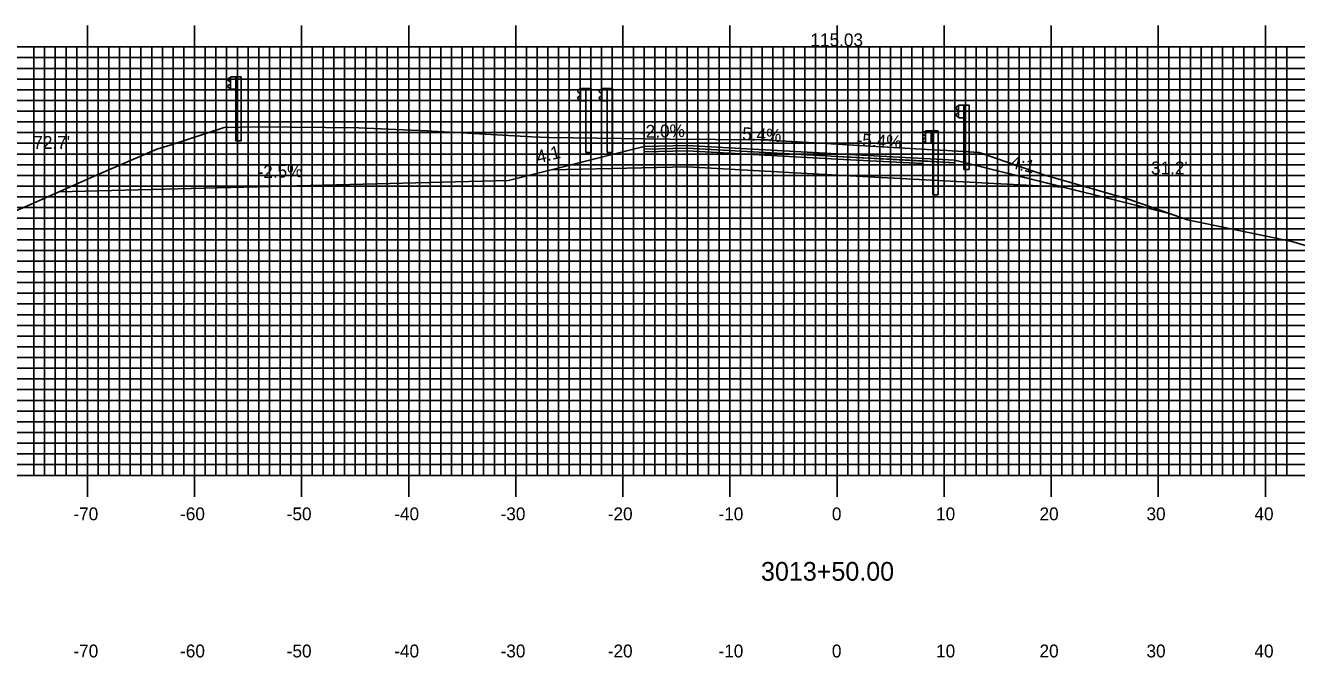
# Model space of a CAD drawing. Extents: x 1684405 to 1684749, y 461260 to 461480.
# Drawn here: x 1684495.4 to 1684614.1, y 461326.1 to 461385.1 of the extents above; entities that cross this region are included whole.
import ezdxf

# ---------------------------------------------------------------- set-up
doc = ezdxf.new("R2010")
doc.units = 0
for name, color, linetype in [('ANNOTATION', 7, 'Continuous'), ('D_Guardrail_Beam_Rt', 7, 'Continuous'), ('D_Roadway_Centerline', 7, 'Continuous'), ('D_Roadway_Centerline_Text', 7, 'Continuous'), ('D_Roadway_Edge_Shoulder', 7, 'Continuous'), ('D_Roadway_Edge_TW', 7, 'Continuous'), ('D_Roadway_Pavement', 7, 'Continuous'), ('D_Roadway_SlopeLines', 7, 'Continuous'), ('D_Roadway_SubGrade', 7, 'Continuous'), ('D_Text_Standard', 7, 'Continuous'), ('H_V ANNOTATION', 7, 'Continuous'), ('M_Guardrail', 7, 'Continuous'), ('M_Roadway_Centerline', 7, 'Continuous'), ('MAJOR', 7, 'Continuous'), ('MINOR', 7, 'Continuous'), ('S_Roadway_Centerline', 7, 'Continuous')]:
    doc.layers.add(name, color=color, linetype=linetype)

msp = doc.modelspace()

# ---------------------------------------------------------------- linework, layer by layer
at = {"layer": 'D_Guardrail_Beam_Rt'}
for p, q in [((1684579.38, 461375.15), (1684579.24, 461375.05)), ((1684579.47, 461375.17), (1684579.4, 461375.15)), ((1684579.47, 461375.25), (1684580.16, 461375.25)), ((1684579.47, 461374.09), (1684579.47, 461375.25)), ((1684579.99, 461375.25), (1684579.99, 461374.09)), ((1684580.1, 461375.25), (1684580.1, 461374.09)), ((1684580.16, 461375.25), (1684580.63, 461375.25)), ((1684580.16, 461375.25), (1684580.16, 461374.09)), ((1684580.63, 461375.25), (1684580.63, 461369.25)), ((1684579.24, 461374.9), (1684579.44, 461374.77)), ((1684579.44, 461374.57), (1684579.24, 461374.43)), ((1684579.24, 461374.29), (1684579.38, 461374.19)), ((1684579.4, 461374.18), (1684579.47, 461374.17)), ((1684579.47, 461374.7), (1684579.47, 461374.63)), ((1684580.16, 461374.09), (1684579.47, 461374.09)), ((1684580.14, 461369.25), (1684580.14, 461374.09)), ((1684571.2, 461373.1), (1684582.2, 461372.51)), ((1684571.2, 461372.85), (1684582.19, 461372.26)), ((1684580.14, 461369.25), (1684580.63, 461369.25))]:
    msp.add_line(p, q, dxfattribs=at)
msp.add_lwpolyline([(1684582.2, 461372.51), (1684586.2, 461371.51), (1684602.45, 461367.45)], dxfattribs=at)
for centre, major_axis, start_param, end_param in [((1684579.41, 461375.11), (-0.0417, 0), 4.907132, 5.323254), ((1684579.29, 461374.98), (-0.0877, 0), 5.323254, 7.243116), ((1684579.29, 461374.36), (-0.0877, 0), 5.323254, 7.243116), ((1684579.41, 461374.22), (-0.0417, 0), 0.959931, 1.376053), ((1684579.39, 461374.7), (0.0789, 0), 0, 0.959931), ((1684579.39, 461374.63), (0.0789, 0), 5.323254, 6.283185)]:
    msp.add_ellipse(centre, major_axis=major_axis, ratio=0.995501, start_param=start_param, end_param=end_param, dxfattribs=at)
at = {"layer": 'D_Roadway_Centerline'}
msp.add_lwpolyline([(1684498.54, 461369.55), (1684540.51, 461370.6), (1684544.51, 461371.6), (1684553.2, 461373.78), (1684557.2, 461373.86), (1684571.2, 461373.1), (1684582.2, 461372.51), (1684602.45, 461367.45)], dxfattribs=at)
at = {"layer": 'D_Roadway_Edge_Shoulder'}
for points in [[(1684557.2, 461373.86), (1684553.2, 461373.78), (1684553.2, 461373.53), (1684557.2, 461373.61)], [(1684571.2, 461373.1), (1684582.2, 461372.51), (1684582.2, 461372.26), (1684571.2, 461372.85)], [(1684571.2, 461372.85), (1684579.2, 461372.42), (1684579.2, 461372.17), (1684571.2, 461372.6)]]:
    msp.add_lwpolyline(points, close=True, dxfattribs=at)
at = {"layer": 'D_Roadway_Edge_TW'}
msp.add_lwpolyline([(1684557.2, 461373.86), (1684571.2, 461373.1), (1684571.2, 461372.85), (1684557.2, 461373.61)], close=True, dxfattribs=at)
at = {"layer": 'D_Roadway_Pavement'}
for points in [[(1684557.2, 461373.61), (1684553.2, 461373.53), (1684553.2, 461373.28), (1684557.2, 461373.36)], [(1684557.2, 461373.61), (1684571.2, 461372.85), (1684571.2, 461372.6), (1684557.2, 461373.36)]]:
    msp.add_lwpolyline(points, close=True, dxfattribs=at)
msp.add_lwpolyline([(1684571.2, 461372.85), (1684571.2, 461372.6)], dxfattribs=at)
msp.add_lwpolyline([(1684571.2, 461372.85), (1684571.2, 461372.6)], dxfattribs=at)
at = {"layer": 'D_Roadway_SlopeLines'}
msp.add_line((1684582.2, 461372.51), (1684582.2, 461372.51), dxfattribs=at)
for points in [[(1684553.2, 461373.78), (1684540.51, 461370.6)], [(1684540.51, 461370.6), (1684498.54, 461369.55)]]:
    msp.add_lwpolyline(points, dxfattribs=at)
at = {"layer": 'D_Roadway_SubGrade'}
for points in [[(1684557.2, 461373.36), (1684553.2, 461373.28), (1684553.2, 461373.53), (1684553.2, 461373.78), (1684544.51, 461371.6), (1684557.2, 461371.86)], [(1684557.2, 461373.36), (1684571.2, 461372.6), (1684571.2, 461371.1), (1684557.2, 461371.86)], [(1684571.2, 461372.6), (1684571.2, 461372.85), (1684579.2, 461372.42), (1684582.2, 461372.26), (1684582.2, 461372.51), (1684592.38, 461369.96), (1684571.2, 461371.1)]]:
    msp.add_lwpolyline(points, close=True, dxfattribs=at)
at = {"layer": 'M_Guardrail'}
for p, q in [((1684514.47, 461380.19), (1684514.33, 461380.09)), ((1684514.33, 461379.95), (1684514.52, 461379.82)), ((1684514.57, 461380.22), (1684514.49, 461380.2)), ((1684514.57, 461380.29), (1684515.06, 461380.29)), ((1684514.57, 461379.12), (1684514.57, 461380.29)), ((1684515.06, 461380.29), (1684515.55, 461380.29)), ((1684515.06, 461380.29), (1684515.06, 461379.12)), ((1684515.55, 461380.29), (1684515.55, 461374.29)), ((1684514.52, 461379.6), (1684514.33, 461379.46)), ((1684514.33, 461379.32), (1684514.47, 461379.22)), ((1684514.49, 461379.21), (1684514.57, 461379.19)), ((1684514.56, 461379.75), (1684514.56, 461379.66)), ((1684515.06, 461379.12), (1684514.57, 461379.12)), ((1684515.06, 461374.29), (1684515.06, 461379.12)), ((1684547.15, 461379.11), (1684547, 461379.01)), ((1684547, 461378.86), (1684547.2, 461378.73)), ((1684547.25, 461379.13), (1684547.17, 461379.11)), ((1684547.25, 461379.2), (1684547.74, 461379.2)), ((1684547.25, 461378.03), (1684547.25, 461379.2)), ((1684547.74, 461379.2), (1684548.23, 461379.2)), ((1684547.74, 461379.2), (1684547.74, 461378.03)), ((1684548.23, 461379.2), (1684548.23, 461373.2)), ((1684549.15, 461379.11), (1684549.01, 461379.01)), ((1684549.01, 461378.86), (1684549.2, 461378.73)), ((1684549.25, 461379.13), (1684549.17, 461379.11)), ((1684549.25, 461379.2), (1684549.74, 461379.2)), ((1684549.25, 461378.03), (1684549.25, 461379.2)), ((1684549.74, 461379.2), (1684550.23, 461379.2)), ((1684549.74, 461379.2), (1684549.74, 461378.03)), ((1684550.23, 461379.2), (1684550.23, 461373.2)), ((1684547.2, 461378.51), (1684547, 461378.37)), ((1684547, 461378.23), (1684547.15, 461378.13)), ((1684547.17, 461378.12), (1684547.25, 461378.11)), ((1684547.23, 461378.66), (1684547.23, 461378.57)), ((1684547.74, 461378.03), (1684547.25, 461378.03)), ((1684547.74, 461373.2), (1684547.74, 461378.03)), ((1684549.2, 461378.51), (1684549.01, 461378.37)), ((1684549.01, 461378.23), (1684549.15, 461378.13)), ((1684549.17, 461378.12), (1684549.25, 461378.11)), ((1684549.23, 461378.66), (1684549.23, 461378.57)), ((1684549.74, 461378.03), (1684549.25, 461378.03)), ((1684549.74, 461373.2), (1684549.74, 461378.03)), ((1684582.46, 461377.53), (1684582.31, 461377.43)), ((1684582.55, 461377.56), (1684582.47, 461377.54)), ((1684582.55, 461377.63), (1684583.04, 461377.63)), ((1684582.55, 461376.46), (1684582.55, 461377.63)), ((1684583.04, 461377.63), (1684583.54, 461377.63)), ((1684583.04, 461377.63), (1684583.04, 461376.46)), ((1684583.54, 461377.63), (1684583.54, 461371.63)), ((1684582.31, 461377.29), (1684582.51, 461377.15)), ((1684582.51, 461376.93), (1684582.31, 461376.8)), ((1684582.31, 461376.66), (1684582.46, 461376.56)), ((1684582.47, 461376.55), (1684582.55, 461376.53)), ((1684582.54, 461377.09), (1684582.54, 461377)), ((1684583.04, 461376.46), (1684582.55, 461376.46)), ((1684583.04, 461371.63), (1684583.04, 461376.46)), ((1684515.06, 461374.29), (1684515.55, 461374.29)), ((1684547.74, 461373.2), (1684548.23, 461373.2)), ((1684549.74, 461373.2), (1684550.23, 461373.2)), ((1684583.04, 461371.63), (1684583.54, 461371.63))]:
    msp.add_line(p, q, dxfattribs=at)
for centre, major_axis, start_param, end_param in [((1684514.38, 461380.02), (-0.0877, 0), 5.323254, 7.243116), ((1684514.5, 461380.16), (-0.0417, 0), 4.886922, 5.323254), ((1684514.38, 461379.39), (-0.0877, 0), 5.323254, 7.243116), ((1684514.5, 461379.25), (-0.0417, 0), 0.959931, 1.396263), ((1684514.48, 461379.75), (0.0789, 0), 0, 0.959931), ((1684514.48, 461379.66), (0.0789, 0), 5.323254, 6.283185), ((1684547.06, 461378.94), (-0.0877, 0), 5.323254, 7.243116), ((1684547.17, 461379.07), (-0.0417, 0), 4.886922, 5.323254), ((1684547.16, 461378.66), (0.0789, 0), 0, 0.959931), ((1684549.06, 461378.94), (-0.0877, 0), 5.323254, 7.243116), ((1684549.17, 461379.07), (-0.0417, 0), 4.886922, 5.323254), ((1684549.16, 461378.66), (0.0789, 0), 0, 0.959931), ((1684547.06, 461378.3), (-0.0877, 0), 5.323254, 7.243116), ((1684547.17, 461378.16), (-0.0417, 0), 0.959931, 1.396263), ((1684547.16, 461378.57), (0.0789, 0), 5.323254, 6.283185), ((1684549.06, 461378.3), (-0.0877, 0), 5.323254, 7.243116), ((1684549.17, 461378.16), (-0.0417, 0), 0.959931, 1.396263), ((1684549.16, 461378.57), (0.0789, 0), 5.323254, 6.283185), ((1684582.48, 461377.5), (-0.0417, 0), 4.886922, 5.323254), ((1684582.36, 461377.36), (-0.0877, 0), 5.323254, 7.243116), ((1684582.36, 461376.73), (-0.0877, 0), 5.323254, 7.243116), ((1684582.48, 461376.59), (-0.0417, 0), 0.959931, 1.396263), ((1684582.46, 461377.09), (0.0789, 0), 0, 0.959931), ((1684582.46, 461377), (0.0789, 0), 5.323254, 6.283185)]:
    msp.add_ellipse(centre, major_axis=major_axis, ratio=0.995501, start_param=start_param, end_param=end_param, dxfattribs=at)
at = {"layer": 'MAJOR'}
for p, q in [((1684501.2, 461385.08), (1684501.2, 461383.07)), ((1684511.2, 461385.08), (1684511.2, 461383.07)), ((1684521.2, 461385.08), (1684521.2, 461383.07)), ((1684531.2, 461385.08), (1684531.2, 461383.07)), ((1684541.2, 461385.08), (1684541.2, 461383.07)), ((1684551.2, 461385.08), (1684551.2, 461383.07)), ((1684561.2, 461385.08), (1684561.2, 461383.07)), ((1684571.2, 461385.08), (1684571.2, 461383.07)), ((1684581.2, 461385.08), (1684581.2, 461383.07)), ((1684591.2, 461385.08), (1684591.2, 461383.07)), ((1684601.2, 461385.08), (1684601.2, 461383.07)), ((1684611.2, 461385.08), (1684611.2, 461383.07)), ((1684431.2, 461383.07), (1684711.2, 461383.07)), ((1684431.2, 461383.07), (1684711.2, 461383.07)), ((1684501.2, 461343.07), (1684501.2, 461383.07)), ((1684511.2, 461343.07), (1684511.2, 461383.07)), ((1684521.2, 461343.07), (1684521.2, 461383.07)), ((1684531.2, 461343.07), (1684531.2, 461383.07)), ((1684541.2, 461343.07), (1684541.2, 461383.07)), ((1684551.2, 461343.07), (1684551.2, 461383.07)), ((1684561.2, 461343.07), (1684561.2, 461383.07)), ((1684571.2, 461343.07), (1684571.2, 461383.07)), ((1684581.2, 461343.07), (1684581.2, 461383.07)), ((1684591.2, 461343.07), (1684591.2, 461383.07)), ((1684601.2, 461343.07), (1684601.2, 461383.07)), ((1684611.2, 461343.07), (1684611.2, 461383.07)), ((1684431.2, 461378.07), (1684711.2, 461378.07)), ((1684431.2, 461373.07), (1684711.2, 461373.07)), ((1684431.2, 461368.07), (1684711.2, 461368.07)), ((1684431.2, 461363.07), (1684711.2, 461363.07)), ((1684431.2, 461358.07), (1684711.2, 461358.07)), ((1684431.2, 461353.07), (1684711.2, 461353.07)), ((1684431.2, 461348.07), (1684711.2, 461348.07)), ((1684431.2, 461343.07), (1684711.2, 461343.07)), ((1684431.2, 461343.07), (1684711.2, 461343.07)), ((1684501.2, 461341.07), (1684501.2, 461343.07)), ((1684511.2, 461341.07), (1684511.2, 461343.07)), ((1684521.2, 461341.07), (1684521.2, 461343.07)), ((1684531.2, 461341.07), (1684531.2, 461343.07)), ((1684541.2, 461341.07), (1684541.2, 461343.07)), ((1684551.2, 461341.07), (1684551.2, 461343.07)), ((1684561.2, 461341.07), (1684561.2, 461343.07)), ((1684571.2, 461341.07), (1684571.2, 461343.07)), ((1684581.2, 461341.07), (1684581.2, 461343.07)), ((1684591.2, 461341.07), (1684591.2, 461343.07)), ((1684601.2, 461341.07), (1684601.2, 461343.07)), ((1684611.2, 461341.07), (1684611.2, 461343.07))]:
    msp.add_line(p, q, dxfattribs=at)
at = {"layer": 'MINOR'}
for p, q in [((1684496.2, 461343.07), (1684496.2, 461383.07)), ((1684497.2, 461343.07), (1684497.2, 461383.07)), ((1684498.2, 461343.07), (1684498.2, 461383.07)), ((1684499.2, 461343.07), (1684499.2, 461383.07)), ((1684500.2, 461343.07), (1684500.2, 461383.07)), ((1684502.2, 461343.07), (1684502.2, 461383.07)), ((1684503.2, 461343.07), (1684503.2, 461383.07)), ((1684504.2, 461343.07), (1684504.2, 461383.07)), ((1684505.2, 461343.07), (1684505.2, 461383.07)), ((1684506.2, 461343.07), (1684506.2, 461383.07)), ((1684507.2, 461343.07), (1684507.2, 461383.07)), ((1684508.2, 461343.07), (1684508.2, 461383.07)), ((1684509.2, 461343.07), (1684509.2, 461383.07)), ((1684510.2, 461343.07), (1684510.2, 461383.07)), ((1684512.2, 461343.07), (1684512.2, 461383.07)), ((1684513.2, 461343.07), (1684513.2, 461383.07)), ((1684514.2, 461343.07), (1684514.2, 461383.07)), ((1684515.2, 461343.07), (1684515.2, 461383.07)), ((1684516.2, 461343.07), (1684516.2, 461383.07)), ((1684517.2, 461343.07), (1684517.2, 461383.07)), ((1684518.2, 461343.07), (1684518.2, 461383.07)), ((1684519.2, 461343.07), (1684519.2, 461383.07)), ((1684520.2, 461343.07), (1684520.2, 461383.07)), ((1684522.2, 461343.07), (1684522.2, 461383.07)), ((1684523.2, 461343.07), (1684523.2, 461383.07)), ((1684524.2, 461343.07), (1684524.2, 461383.07)), ((1684525.2, 461343.07), (1684525.2, 461383.07)), ((1684526.2, 461343.07), (1684526.2, 461383.07)), ((1684527.2, 461343.07), (1684527.2, 461383.07)), ((1684528.2, 461343.07), (1684528.2, 461383.07)), ((1684529.2, 461343.07), (1684529.2, 461383.07)), ((1684530.2, 461343.07), (1684530.2, 461383.07)), ((1684532.2, 461343.07), (1684532.2, 461383.07)), ((1684533.2, 461343.07), (1684533.2, 461383.07)), ((1684534.2, 461343.07), (1684534.2, 461383.07)), ((1684535.2, 461343.07), (1684535.2, 461383.07)), ((1684536.2, 461343.07), (1684536.2, 461383.07)), ((1684537.2, 461343.07), (1684537.2, 461383.07)), ((1684538.2, 461343.07), (1684538.2, 461383.07)), ((1684539.2, 461343.07), (1684539.2, 461383.07)), ((1684540.2, 461343.07), (1684540.2, 461383.07)), ((1684542.2, 461343.07), (1684542.2, 461383.07)), ((1684543.2, 461343.07), (1684543.2, 461383.07)), ((1684544.2, 461343.07), (1684544.2, 461383.07)), ((1684545.2, 461343.07), (1684545.2, 461383.07)), ((1684546.2, 461343.07), (1684546.2, 461383.07)), ((1684547.2, 461343.07), (1684547.2, 461383.07)), ((1684548.2, 461343.07), (1684548.2, 461383.07)), ((1684549.2, 461343.07), (1684549.2, 461383.07)), ((1684550.2, 461343.07), (1684550.2, 461383.07)), ((1684552.2, 461343.07), (1684552.2, 461383.07)), ((1684553.2, 461343.07), (1684553.2, 461383.07)), ((1684554.2, 461343.07), (1684554.2, 461383.07)), ((1684555.2, 461343.07), (1684555.2, 461383.07)), ((1684556.2, 461343.07), (1684556.2, 461383.07)), ((1684557.2, 461343.07), (1684557.2, 461383.07)), ((1684558.2, 461343.07), (1684558.2, 461383.07)), ((1684559.2, 461343.07), (1684559.2, 461383.07)), ((1684560.2, 461343.07), (1684560.2, 461383.07)), ((1684562.2, 461343.07), (1684562.2, 461383.07)), ((1684563.2, 461343.07), (1684563.2, 461383.07)), ((1684564.2, 461343.07), (1684564.2, 461383.07)), ((1684565.2, 461343.07), (1684565.2, 461383.07)), ((1684566.2, 461343.07), (1684566.2, 461383.07)), ((1684567.2, 461343.07), (1684567.2, 461383.07)), ((1684568.2, 461343.07), (1684568.2, 461383.07)), ((1684569.2, 461343.07), (1684569.2, 461383.07)), ((1684570.2, 461343.07), (1684570.2, 461383.07)), ((1684572.2, 461343.07), (1684572.2, 461383.07)), ((1684573.2, 461343.07), (1684573.2, 461383.07)), ((1684574.2, 461343.07), (1684574.2, 461383.07)), ((1684575.2, 461343.07), (1684575.2, 461383.07)), ((1684576.2, 461343.07), (1684576.2, 461383.07)), ((1684577.2, 461343.07), (1684577.2, 461383.07)), ((1684578.2, 461343.07), (1684578.2, 461383.07)), ((1684579.2, 461343.07), (1684579.2, 461383.07)), ((1684580.2, 461343.07), (1684580.2, 461383.07)), ((1684582.2, 461343.07), (1684582.2, 461383.07)), ((1684583.2, 461343.07), (1684583.2, 461383.07)), ((1684584.2, 461343.07), (1684584.2, 461383.07)), ((1684585.2, 461343.07), (1684585.2, 461383.07)), ((1684586.2, 461343.07), (1684586.2, 461383.07)), ((1684587.2, 461343.07), (1684587.2, 461383.07)), ((1684588.2, 461343.07), (1684588.2, 461383.07)), ((1684589.2, 461343.07), (1684589.2, 461383.07)), ((1684590.2, 461343.07), (1684590.2, 461383.07)), ((1684592.2, 461343.07), (1684592.2, 461383.07)), ((1684593.2, 461343.07), (1684593.2, 461383.07)), ((1684594.2, 461343.07), (1684594.2, 461383.07)), ((1684595.2, 461343.07), (1684595.2, 461383.07)), ((1684596.2, 461343.07), (1684596.2, 461383.07)), ((1684597.2, 461343.07), (1684597.2, 461383.07)), ((1684598.2, 461343.07), (1684598.2, 461383.07)), ((1684599.2, 461343.07), (1684599.2, 461383.07)), ((1684600.2, 461343.07), (1684600.2, 461383.07)), ((1684602.2, 461343.07), (1684602.2, 461383.07)), ((1684603.2, 461343.07), (1684603.2, 461383.07)), ((1684604.2, 461343.07), (1684604.2, 461383.07)), ((1684605.2, 461343.07), (1684605.2, 461383.07)), ((1684606.2, 461343.07), (1684606.2, 461383.07)), ((1684607.2, 461343.07), (1684607.2, 461383.07)), ((1684608.2, 461343.07), (1684608.2, 461383.07)), ((1684609.2, 461343.07), (1684609.2, 461383.07)), ((1684610.2, 461343.07), (1684610.2, 461383.07)), ((1684612.2, 461343.07), (1684612.2, 461383.07)), ((1684613.2, 461343.07), (1684613.2, 461383.07)), ((1684431.2, 461382.07), (1684711.2, 461382.07)), ((1684431.2, 461381.07), (1684711.2, 461381.07)), ((1684431.2, 461380.07), (1684711.2, 461380.07)), ((1684431.2, 461379.07), (1684711.2, 461379.07)), ((1684431.2, 461377.07), (1684711.2, 461377.07)), ((1684431.2, 461376.07), (1684711.2, 461376.07)), ((1684431.2, 461375.07), (1684711.2, 461375.07)), ((1684431.2, 461374.07), (1684711.2, 461374.07)), ((1684431.2, 461372.07), (1684711.2, 461372.07)), ((1684431.2, 461371.07), (1684711.2, 461371.07)), ((1684431.2, 461370.07), (1684711.2, 461370.07)), ((1684431.2, 461369.07), (1684711.2, 461369.07)), ((1684431.2, 461367.07), (1684711.2, 461367.07)), ((1684431.2, 461366.07), (1684711.2, 461366.07)), ((1684431.2, 461365.07), (1684711.2, 461365.07)), ((1684431.2, 461364.07), (1684711.2, 461364.07)), ((1684431.2, 461362.07), (1684711.2, 461362.07)), ((1684431.2, 461361.07), (1684711.2, 461361.07)), ((1684431.2, 461360.07), (1684711.2, 461360.07)), ((1684431.2, 461359.07), (1684711.2, 461359.07)), ((1684431.2, 461357.07), (1684711.2, 461357.07)), ((1684431.2, 461356.07), (1684711.2, 461356.07)), ((1684431.2, 461355.07), (1684711.2, 461355.07)), ((1684431.2, 461354.07), (1684711.2, 461354.07)), ((1684431.2, 461352.07), (1684711.2, 461352.07)), ((1684431.2, 461351.07), (1684711.2, 461351.07)), ((1684431.2, 461350.07), (1684711.2, 461350.07)), ((1684431.2, 461349.07), (1684711.2, 461349.07)), ((1684431.2, 461347.07), (1684711.2, 461347.07)), ((1684431.2, 461346.07), (1684711.2, 461346.07)), ((1684431.2, 461345.07), (1684711.2, 461345.07)), ((1684431.2, 461344.07), (1684711.2, 461344.07))]:
    msp.add_line(p, q, dxfattribs=at)
at = {"layer": 'S_Roadway_Centerline'}
msp.add_lwpolyline([(1684479.27, 461361.19), (1684495.89, 461368.37), (1684502.06, 461371.11), (1684507.69, 461373.52), (1684508.92, 461373.91), (1684513.97, 461375.55), (1684517.17, 461375.6), (1684526.55, 461375.51), (1684531.4, 461375.3), (1684532.97, 461375.24), (1684533.36, 461375.21), (1684539.46, 461374.85), (1684542.67, 461374.66), (1684544.3, 461374.61), (1684555.55, 461374.47), (1684564.09, 461374.41), (1684564.79, 461374.38), (1684565.35, 461374.34), (1684579.63, 461373.49), (1684581.45, 461373.39), (1684584.47, 461373.2), (1684590.5, 461371.13), (1684598.43, 461368.86), (1684603.93, 461366.92), (1684613.66, 461364.89), (1684632.38, 461359.36)], dxfattribs=at)

# ---------------------------------------------------------------- texts
at = {"layer": 'ANNOTATION'}
for s, rotation, p in [('-2.0%', 1.1458, (1684552.81, 461374.57)), ('5.4%', 356.909, (1684562.32, 461374.38)), ('-5.4%', 356.909, (1684573, 461373.81)), ('4:1', 14.0362, (1684543.3, 461372.18)), ('4:1', 345.9638, (1684587.32, 461371.8)), ('-2.5%', 1.4415, (1684517.1, 461370.81))]:
    msp.add_text(s, height=1.2, rotation=rotation, dxfattribs=at).set_placement(p)
at = {"layer": 'D_Roadway_Centerline_Text'}
msp.add_text('115.03', height=1.2, dxfattribs=at).set_placement((1684568.72, 461383.13))
at = {"layer": 'D_Text_Standard'}
for s, p in [("72.7'", (1684496.15, 461373.55)), ("31.2'", (1684600.52, 461371.17))]:
    msp.add_text(s, height=1.2, dxfattribs=at).set_placement(p)
at = {"layer": 'H_V ANNOTATION'}
for s, height, p in [('-70', 1.2, (1684499.89, 461338.87)), ('-60', 1.2, (1684509.85, 461338.87)), ('-50', 1.2, (1684519.81, 461338.87)), ('-40', 1.2, (1684529.85, 461338.87)), ('-30', 1.2, (1684539.78, 461338.87)), ('-20', 1.2, (1684549.79, 461338.87)), ('-10', 1.2, (1684560.13, 461338.87)), ('0', 1.2, (1684570.72, 461338.87)), ('10', 1.2, (1684580.45, 461338.87)), ('20', 1.2, (1684590.11, 461338.87)), ('30', 1.2, (1684600.1, 461338.87)), ('40', 1.2, (1684610.18, 461338.87)), ('3013+50.00', 1.75, (1684564.1, 461333.23)), ('-70', 1.2, (1684499.89, 461326.07)), ('-60', 1.2, (1684509.85, 461326.07)), ('-50', 1.2, (1684519.81, 461326.07)), ('-40', 1.2, (1684529.85, 461326.07)), ('-30', 1.2, (1684539.78, 461326.07)), ('-20', 1.2, (1684549.79, 461326.07)), ('-10', 1.2, (1684560.13, 461326.07)), ('0', 1.2, (1684570.72, 461326.07)), ('10', 1.2, (1684580.45, 461326.07)), ('20', 1.2, (1684590.11, 461326.07)), ('30', 1.2, (1684600.1, 461326.07)), ('40', 1.2, (1684610.18, 461326.07))]:
    msp.add_text(s, height=height, dxfattribs=at).set_placement(p)
at = {"layer": 'M_Roadway_Centerline'}
for s, p in [('C', (1684532.97, 461375.24)), ('L', (1684532.97, 461375.23)), ('C', (1684564.79, 461374.38)), ('L', (1684564.79, 461374.37))]:
    msp.add_text(s, height=0.0146, dxfattribs=at).set_placement(p)

doc.saveas('drawing.dxf')
